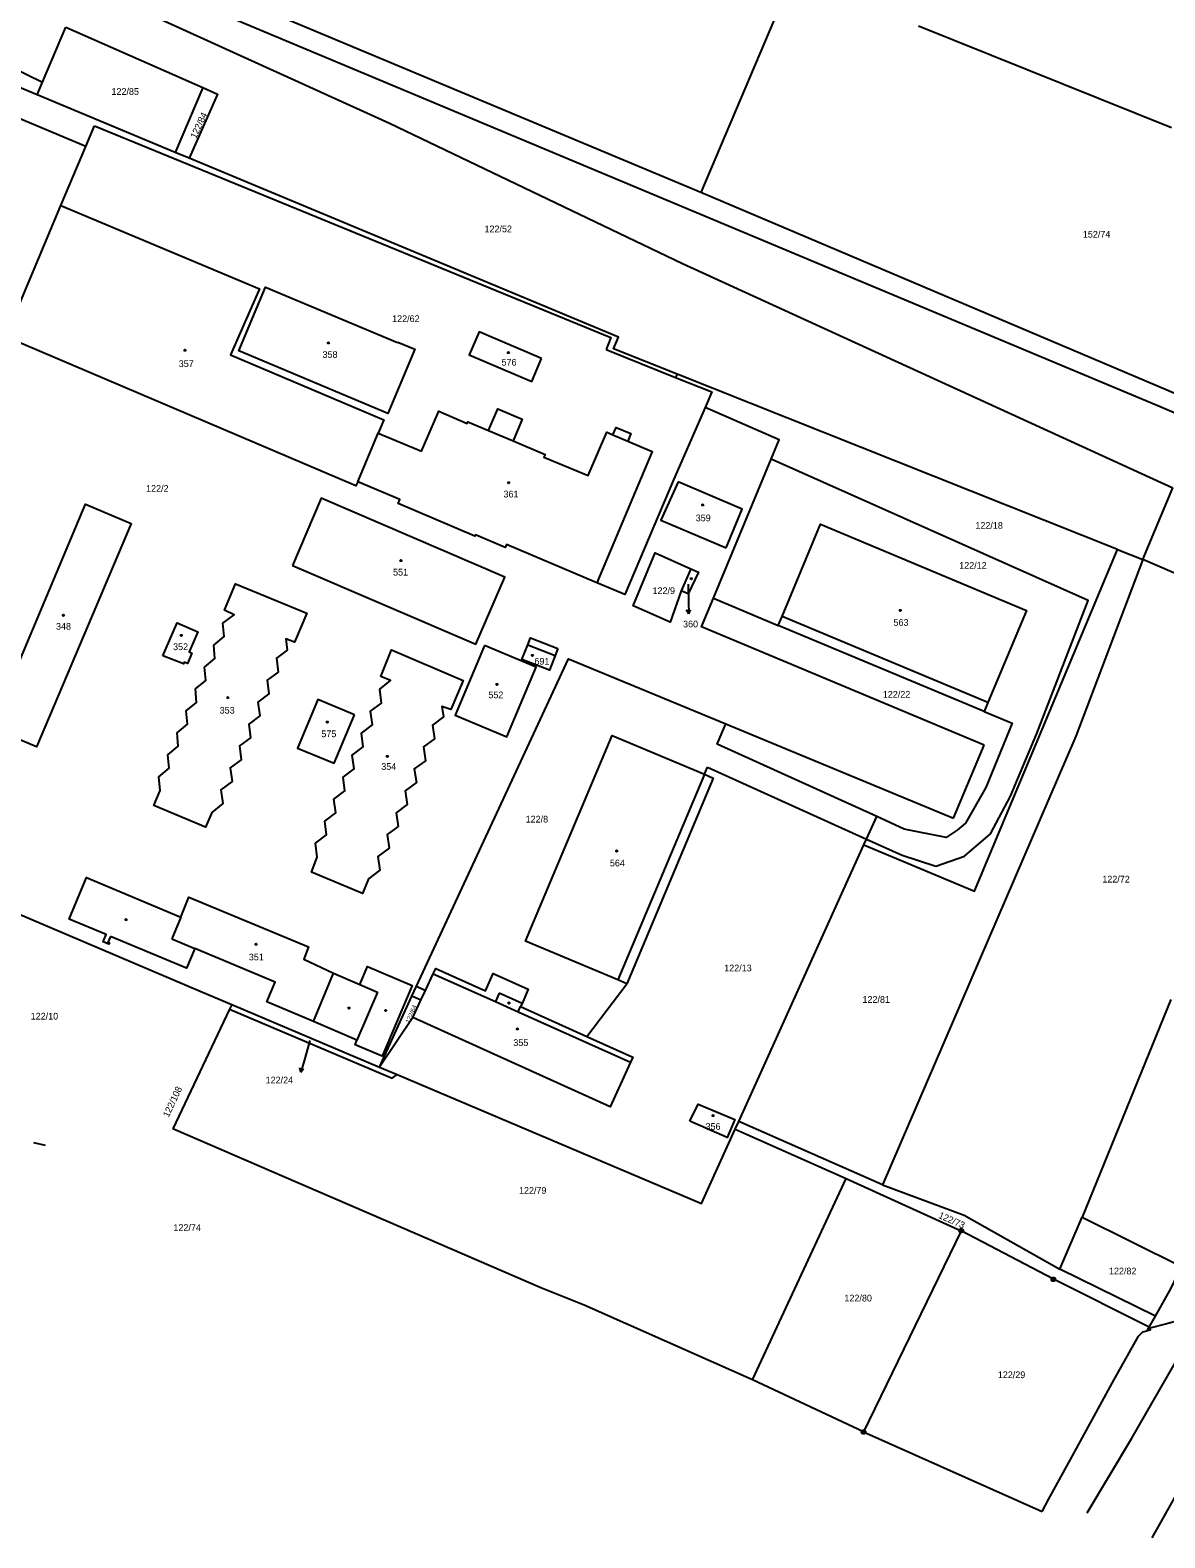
# Model space of a CAD drawing. Extents: x -783948 to -781889, y -1005870 to -1004430.
# Drawn here: x -783525.7 to -783238.5, y -1005192 to -1004810.4 of the extents above; entities that cross this region are included whole.
import ezdxf

# ---------------------------------------------------------------- set-up
doc = ezdxf.new("R2010")
doc.units = 0
for name, color, linetype in [('Vrstva 1', 7, 'Continuous'), ('Vrstva 2', 7, 'Continuous'), ('Vrstva 4', 7, 'Continuous'), ('Vrstva 5', 7, 'Continuous'), ('Vrstva 6', 7, 'Continuous'), ('Vrstva 7', 7, 'Continuous'), ('Vrstva 8', 7, 'Continuous')]:
    doc.layers.add(name, color=color, linetype=linetype)

msp = doc.modelspace()

# ---------------------------------------------------------------- linework, layer by layer
at = {"layer": 'Vrstva 1'}
for p, q in [((-783616.88, -1004777.22), (-783522.54, -1004823.62)), ((-783333.26, -1004797.89), (-783355.91, -1004851.55)), ((-783522.54, -1004823.62), (-783516.61, -1004809.65)), ((-783516.61, -1004809.65), (-783481.95, -1004824.95)), ((-783300.84, -1004809.34), (-783236.85, -1004835.1)), ((-783511.57, -1004839.9), (-783545.36, -1004825.67)), ((-783523.89, -1004826.8), (-783522.54, -1004823.62)), ((-783481.95, -1004824.95), (-783488.93, -1004841.36)), ((-783488.93, -1004841.36), (-783523.89, -1004826.8)), ((-783511.57, -1004839.9), (-783509.36, -1004834.66)), ((-783517.86, -1004854.84), (-783511.57, -1004839.9)), ((-783485.39, -1004842.84), (-783488.93, -1004841.36)), ((-783176.87, -1004927.54), (-783355.91, -1004851.55)), ((-783379.94, -1004891.29), (-783362.32, -1004898.32)), ((-783361.96, -1004897.48), (-783362.32, -1004898.32)), ((-783250.52, -1004941.88), (-783361.96, -1004897.48)), ((-783354.89, -1004905.91), (-783362.87, -1004924.27)), ((-783442.78, -1004924.72), (-783437.56, -1004912.44)), ((-783352.76, -1004954.19), (-783338.15, -1004919.02)), ((-783244.08, -1004944.4), (-783236.49, -1004926.3)), ((-783250.52, -1004941.88), (-783244.08, -1004944.4)), ((-783197.55, -1004964.59), (-783244.08, -1004944.4)), ((-783358.47, -1004946.76), (-783360.89, -1004952.36)), ((-783352.76, -1004954.19), (-783336.36, -1004961.06)), ((-783284.27, -1004982.87), (-783336.36, -1004961.06)), ((-783349.66, -1004986), (-783292, -1005009.86)), ((-783292, -1005009.86), (-783284.27, -1004991.41)), ((-783355.04, -1004998.76), (-783354.26, -1004996.92)), ((-783354.26, -1004996.92), (-783314.01, -1005015.14)), ((-783314.01, -1005015.14), (-783311.44, -1005009.45)), ((-783346.37, -1005086.59), (-783314.69, -1005016.63)), ((-783314.69, -1005016.63), (-783314.01, -1005015.14)), ((-783533.85, -1005031.91), (-783482.02, -1005053.88)), ((-783482.02, -1005053.88), (-783474.65, -1005057.01)), ((-783437.27, -1005072.86), (-783429.08, -1005054.87)), ((-783429.08, -1005054.87), (-783427.93, -1005052.4)), ((-783384.77, -1005065.1), (-783374.68, -1005051.77)), ((-783475.21, -1005058.19), (-783489.52, -1005088.45)), ((-783474.65, -1005057.01), (-783475.21, -1005058.19)), ((-783474.65, -1005057.01), (-783437.27, -1005072.86)), ((-783237.05, -1005055.76), (-783259.43, -1005110.88)), ((-783428.84, -1005060.34), (-783437.27, -1005072.86)), ((-783437.27, -1005072.86), (-783432.8, -1005074.75)), ((-783461.46, -1005100.61), (-783489.52, -1005088.45)), ((-783347.28, -1005088.6), (-783346.37, -1005086.59)), ((-783347.28, -1005088.6), (-783319.15, -1005101.07)), ((-783309.97, -1005102.63), (-783346.37, -1005086.59)), ((-783524.82, -1005091.94), (-783521.86, -1005092.63)), ((-783431.98, -1005113.38), (-783461.46, -1005100.61)), ((-783342.85, -1005152), (-783319.15, -1005101.07)), ((-783319.15, -1005101.07), (-783290.07, -1005114.26)), ((-783265.13, -1005123.98), (-783259.43, -1005110.88)), ((-783259.43, -1005110.88), (-783234.31, -1005123.3)), ((-783396.48, -1005128.76), (-783431.98, -1005113.38)), ((-783290.07, -1005114.26), (-783314.77, -1005165.21)), ((-783240.91, -1005135.88), (-783265.13, -1005123.98)), ((-783242.99, -1005139.6), (-783242.49, -1005138.71)), ((-783314.77, -1005165.21), (-783342.85, -1005152)), ((-783314.77, -1005165.21), (-783269.58, -1005185.36)), ((-783269.58, -1005185.36), (-783267.94, -1005182.33))]:
    msp.add_line(p, q, dxfattribs=at)
for points in [[(-783355.91, -1004851.55), (-783501.59, -1004790.51), (-783555.37, -1004767.38)], [(-783512.01, -1004798.82), (-783434.77, -1004833.99), (-783360.56, -1004869.48), (-783236.49, -1004926.3)], [(-783523.89, -1004826.8), (-783558.98, -1004812.17), (-783592.76, -1004850.42)], [(-783481.95, -1004824.95), (-783478.25, -1004826.59), (-783485.39, -1004842.84)], [(-783509.36, -1004834.66), (-783378.69, -1004888.25), (-783379.94, -1004891.29)], [(-783361.96, -1004897.48), (-783378.03, -1004891.08), (-783376.78, -1004888.09), (-783485.39, -1004842.84)], [(-783442.78, -1004924.72), (-783443.21, -1004925.73), (-783531.85, -1004888.01), (-783517.86, -1004854.84)], [(-783517.86, -1004854.84), (-783467.66, -1004875.89), (-783474.96, -1004892.58), (-783436.13, -1004909.08), (-783437.56, -1004912.44)], [(-783432.63, -1004889.37), (-783428.31, -1004891.18), (-783435.16, -1004907.48), (-783472.89, -1004891.61), (-783466.15, -1004875.51), (-783432.69, -1004889.51), (-783432.63, -1004889.37)], [(-783396.25, -1004893.54), (-783412.08, -1004886.79), (-783414.57, -1004892.63), (-783398.74, -1004899.38), (-783396.25, -1004893.54)], [(-783362.32, -1004898.32), (-783353.18, -1004901.97), (-783354.89, -1004905.91)], [(-783437.56, -1004912.44), (-783426.62, -1004916.97), (-783422.25, -1004906.84), (-783415.04, -1004909.94), (-783414.87, -1004909.53), (-783409.68, -1004911.74), (-783407.34, -1004906.23), (-783401.13, -1004908.86), (-783403.46, -1004914.38), (-783395.36, -1004917.82), (-783395.65, -1004918.51), (-783384.44, -1004923.17), (-783379.72, -1004912.16), (-783378.19, -1004912.83), (-783377.41, -1004910.99), (-783373.67, -1004912.52), (-783374.42, -1004914.44), (-783368.24, -1004917.1), (-783382.23, -1004950.34)], [(-783338.15, -1004919.02), (-783336.1, -1004914.09), (-783354.89, -1004905.91)], [(-783314.01, -1005015.14), (-783305.01, -1005019.21), (-783296.5, -1005022.01), (-783289.25, -1005019.49), (-783282.64, -1005013.85), (-783277.59, -1005004.29), (-783270.94, -1004988.45), (-783257.95, -1004954.74), (-783338.15, -1004919.02)], [(-783382.23, -1004950.34), (-783405.13, -1004940.56), (-783405.46, -1004941.34), (-783413, -1004938.13), (-783413.16, -1004938.5), (-783432.58, -1004930.25), (-783432.15, -1004929.24), (-783442.78, -1004924.72)], [(-783362.87, -1004924.27), (-783375.15, -1004953.22), (-783382.23, -1004950.34)], [(-783361.72, -1004924.73), (-783366.06, -1004934.41), (-783349.57, -1004941.41)], [(-783349.57, -1004941.41), (-783345.51, -1004931.63), (-783361.72, -1004924.73)], [(-783459.3, -1004945.93), (-783412.89, -1004965.84), (-783405.59, -1004948.83), (-783452, -1004928.91), (-783459.3, -1004945.93)], [(-783535.52, -1004987.01), (-783511.69, -1004930.42), (-783500.14, -1004935.26), (-783524.03, -1004991.84), (-783535.52, -1004987.01)], [(-783336.36, -1004961.06), (-783335.41, -1004958.8), (-783325.63, -1004935.46), (-783273.55, -1004957.29), (-783283.33, -1004980.63), (-783284.27, -1004982.87)], [(-783360.89, -1004952.36), (-783363.75, -1004960.27), (-783373.06, -1004956.1), (-783367.48, -1004942.75), (-783358.47, -1004946.76)], [(-783314.69, -1005016.63), (-783286.72, -1005028.34), (-783250.52, -1004941.88)], [(-783244.08, -1004944.4), (-783261.03, -1004989.09), (-783309.97, -1005102.63)], [(-783358.47, -1004946.76), (-783356.5, -1004947.61), (-783359.16, -1004953.11), (-783360.89, -1004952.36)], [(-783462.92, -1004972.88), (-783465.69, -1004974.95), (-783465.25, -1004978.42), (-783468.03, -1004980.5), (-783467.58, -1004983.97), (-783470.37, -1004986.04), (-783469.91, -1004989.51), (-783472.71, -1004991.59), (-783472.24, -1004995.06), (-783475.05, -1004997.14), (-783474.57, -1005000.6), (-783477.39, -1005002.68), (-783476.9, -1005006.15), (-783479.66, -1005008.39), (-783481.3, -1005012.1), (-783494.35, -1005006.63), (-783492.73, -1005002.87), (-783493.12, -1004999.36), (-783490.49, -1004997.2), (-783490.8, -1004993.81), (-783488.18, -1004991.65), (-783488.48, -1004988.26), (-783485.86, -1004986.1), (-783486.16, -1004982.71), (-783483.54, -1004980.55), (-783483.85, -1004977.16), (-783481.22, -1004975), (-783481.53, -1004971.61), (-783478.91, -1004969.45), (-783479.21, -1004966.06), (-783476.59, -1004963.9), (-783476.9, -1004960.51), (-783474.04, -1004958.41), (-783476.51, -1004957.2), (-783473.69, -1004950.56), (-783455.67, -1004958.02), (-783458.74, -1004965.34), (-783460.99, -1004964.51), (-783460.59, -1004967.33), (-783463.35, -1004969.4), (-783462.92, -1004972.88)], [(-783284.27, -1004991.41), (-783355.77, -1004961.44), (-783352.76, -1004954.19)], [(-783492.05, -1004968.75), (-783488.49, -1004960.42), (-783483.25, -1004962.68), (-783485.41, -1004967.77), (-783484.72, -1004968.07), (-783485.86, -1004970.75), (-783486.65, -1004970.42), (-783486.87, -1004970.83), (-783492.05, -1004968.75)], [(-783432.54, -1005011.94), (-783435.35, -1005014.02), (-783434.84, -1005017.48), (-783437.66, -1005019.56), (-783437.14, -1005023.03), (-783440.05, -1005025.22), (-783441.6, -1005028.9), (-783454.51, -1005023.57), (-783453.04, -1005019.77), (-783453.44, -1005016.21), (-783450.64, -1005014.11), (-783451.12, -1005010.64), (-783448.32, -1005008.54), (-783448.8, -1005005.08), (-783446, -1005002.98), (-783446.48, -1004999.51), (-783443.68, -1004997.41), (-783444.16, -1004993.95), (-783441.36, -1004991.85), (-783441.84, -1004988.38), (-783439.04, -1004986.28), (-783439.52, -1004982.81), (-783436.72, -1004980.72), (-783437.2, -1004977.25), (-783434.44, -1004975.02), (-783436.95, -1004974.04), (-783434.21, -1004967.25), (-783416.06, -1004975.03), (-783419.2, -1004982.4), (-783421.47, -1004981.6), (-783421.04, -1004984.22), (-783423.85, -1004986.3), (-783423.34, -1004989.76), (-783426.15, -1004991.84), (-783425.64, -1004995.31), (-783428.45, -1004997.39), (-783427.94, -1005000.85), (-783430.75, -1005002.93), (-783430.24, -1005006.39), (-783433.05, -1005008.48), (-783432.54, -1005011.94)], [(-783410.73, -1004966.19), (-783418.1, -1004983.81), (-783405.03, -1004989.29), (-783397.65, -1004971.64), (-783410.73, -1004966.19)], [(-783392.14, -1004966.96), (-783392.8, -1004968.7), (-783394.28, -1004972.41), (-783401.25, -1004969.68), (-783399.75, -1004965.98), (-783399.02, -1004964.21), (-783392.14, -1004966.96)], [(-783427.93, -1005052.4), (-783389.47, -1004969.54), (-783349.66, -1004986)], [(-783443.57, -1004983.74), (-783452.88, -1004979.86), (-783457.98, -1004992.11), (-783448.73, -1004995.96), (-783443.57, -1004983.74)], [(-783284.27, -1004982.87), (-783277.16, -1004985.84), (-783283.83, -1005002.13), (-783289, -1005011.14), (-783291.12, -1005012.94), (-783293.86, -1005014.79), (-783304.49, -1005012.61), (-783311.44, -1005009.45)], [(-783311.44, -1005009.45), (-783351.81, -1004991.11), (-783349.66, -1004986)], [(-783374.68, -1005051.77), (-783376.99, -1005050.8), (-783400.32, -1005040.96), (-783378.37, -1004988.92), (-783355.04, -1004998.76)], [(-783355.04, -1004998.76), (-783352.79, -1004999.74), (-783374.68, -1005051.77)], [(-783505.33, -1005039.77), (-783505.97, -1005041.29), (-783505.6, -1005041.45), (-783505.73, -1005041.77), (-783507.16, -1005041.17), (-783506.39, -1005039.33), (-783515.82, -1005035.39), (-783511.38, -1005024.92), (-783487.57, -1005034.88), (-783485.54, -1005029.87), (-783455.27, -1005042.46), (-783456.42, -1005045.52), (-783448.87, -1005049.12), (-783442.25, -1005051.95), (-783440.32, -1005047.4), (-783429, -1005052.2), (-783436.58, -1005070.11), (-783443.42, -1005067.21), (-783442.97, -1005066.02), (-783453.99, -1005061.33), (-783465.74, -1005056.33), (-783463.66, -1005051.36), (-783483.99, -1005042.86), (-783486.07, -1005047.83), (-783505.33, -1005039.77)], [(-783427.93, -1005052.4), (-783425.63, -1005053.48), (-783423.66, -1005049.22), (-783422.97, -1005047.89), (-783410.43, -1005053.56), (-783408.46, -1005049.18), (-783399.61, -1005053.17), (-783401.2, -1005056.79), (-783401.55, -1005057.54), (-783384.77, -1005065.1)], [(-783428.84, -1005060.34), (-783426.78, -1005055.95), (-783429.08, -1005054.87)], [(-783475.21, -1005058.19), (-783434.02, -1005075.66), (-783432.8, -1005074.75)], [(-783384.77, -1005065.1), (-783373.18, -1005070.31), (-783373.77, -1005071.61), (-783378.86, -1005082.88), (-783428.84, -1005060.34)], [(-783432.8, -1005074.75), (-783355.79, -1005107.4), (-783347.28, -1005088.6)], [(-783358.7, -1005086.56), (-783356.64, -1005082.23), (-783347.34, -1005086.16), (-783349.3, -1005090.65), (-783358.7, -1005086.56)], [(-783309.97, -1005102.63), (-783289.28, -1005110.36), (-783265.13, -1005123.98)], [(-783242.49, -1005138.71), (-783266.75, -1005126.57), (-783290.07, -1005114.26)], [(-783240.91, -1005135.88), (-783236.96, -1005128.78), (-783234.31, -1005123.3)], [(-783342.85, -1005152), (-783385.46, -1005133.14), (-783396.48, -1005128.76)], [(-783228.42, -1005135.15), (-783228.69, -1005135.29), (-783238.39, -1005137.89), (-783242.37, -1005138.96), (-783242.28, -1005139.41), (-783242.99, -1005139.6)], [(-783242.49, -1005138.71), (-783241.27, -1005136.52), (-783240.91, -1005135.88)], [(-783267.94, -1005182.33), (-783261.89, -1005171.22), (-783251.85, -1005152.84), (-783245.24, -1005140.99), (-783244.09, -1005139.9), (-783242.99, -1005139.6)]]:
    msp.add_lwpolyline(points, dxfattribs=at)
at = {"layer": 'Vrstva 4'}
for p, q in [((-783409.68, -1004911.74), (-783403.46, -1004914.38)), ((-783378.19, -1004912.83), (-783374.42, -1004914.44)), ((-783283.33, -1004980.63), (-783335.41, -1004958.8)), ((-783399.75, -1004965.98), (-783392.8, -1004968.7)), ((-783355.04, -1004998.76), (-783376.99, -1005050.8)), ((-783487.57, -1005034.88), (-783489.82, -1005040.42)), ((-783489.82, -1005040.42), (-783483.99, -1005042.86)), ((-783453.99, -1005061.33), (-783448.87, -1005049.12)), ((-783423.66, -1005049.22), (-783407.91, -1005056.3)), ((-783437.76, -1005053.87), (-783442.97, -1005066.02)), ((-783442.25, -1005051.95), (-783437.76, -1005053.87)), ((-783426.78, -1005055.95), (-783425.63, -1005053.48)), ((-783406.96, -1005054.19), (-783407.91, -1005056.3)), ((-783401.2, -1005056.79), (-783406.96, -1005054.19)), ((-783407.91, -1005056.3), (-783402.19, -1005058.91)), ((-783402.19, -1005058.91), (-783401.55, -1005057.54)), ((-783402.19, -1005058.91), (-783373.77, -1005071.61)), ((-783246.9, -1005166.76), (-783234.67, -1005145.54)), ((-783258.2, -1005185.66), (-783246.9, -1005166.76)), ((-783231.45, -1005173.48), (-783241.83, -1005192))]:
    msp.add_line(p, q, dxfattribs=at)
at = {"layer": 'Vrstva 5'}
for centre in [(-783486.51, -1004891.44), (-783450.18, -1004889.57), (-783404.65, -1004892.04), (-783404.54, -1004924.98), (-783355.48, -1004930.58), (-783431.85, -1004944.67), (-783358.35, -1004949.27), (-783517.25, -1004958.53), (-783305.49, -1004957.29), (-783487.44, -1004963.62), (-783398.56, -1004968.68), (-783475.64, -1004979.34), (-783407.54, -1004976.03), (-783450.49, -1004985.56), (-783435.28, -1004994.25), (-783377.21, -1005018.17), (-783501.38, -1005035.52), (-783468.5, -1005041.78), (-783445.02, -1005057.94), (-783435.71, -1005058.54), (-783404.52, -1005056.64), (-783402.36, -1005063.21), (-783352.84, -1005085.14)]:
    msp.add_circle(centre, 0.175, dxfattribs=at)
at = {"layer": 'Vrstva 6'}
for p, q in [((-783474.69, -1004807.3), (-783239.72, -1004905.69)), ((-783239.72, -1004905.69), (-783060.19, -1004982.81))]:
    msp.add_line(p, q, dxfattribs=at)
at = {"layer": 'Vrstva 7'}
for p, q in [((-783359.12, -1004950.66), (-783359.07, -1004955.12)), ((-783359.07, -1004955.12), (-783359.02, -1004958.12)), ((-783359.02, -1004958.12), (-783359.54, -1004957.13)), ((-783359.02, -1004958.12), (-783358.53, -1004957.11)), ((-783454.87, -1005066.12), (-783456.36, -1005071.26)), ((-783457.19, -1005074.15), (-783457.39, -1005073.04)), ((-783456.36, -1005071.26), (-783457.19, -1005074.15)), ((-783457.19, -1005074.15), (-783456.43, -1005073.32))]:
    msp.add_line(p, q, dxfattribs=at)
at = {"layer": 'Vrstva 8'}
for centre, radius in [((-783290.07, -1005114.26), 0.5), ((-783290.07, -1005114.26), 0.0303), ((-783266.75, -1005126.57), 0.5), ((-783266.75, -1005126.57), 0.0303), ((-783314.77, -1005165.21), 0.5), ((-783314.77, -1005165.21), 0.0303)]:
    msp.add_circle(centre, radius, dxfattribs=at)

# ---------------------------------------------------------------- texts
at = {"layer": 'Vrstva 2'}
for s, p in [('122/85', (-783505.09, -1004826.81)), ('122/52', (-783410.7, -1004861.58)), ('152/74', (-783259.28, -1004862.94)), ('122/62', (-783434.07, -1004884.31)), ('357', (-783488.07, -1004895.69)), ('358', (-783451.68, -1004893.38)), ('576', (-783406.38, -1004895.33)), ('122/2', (-783496.33, -1004927.26)), ('361', (-783405.89, -1004928.7)), ('359', (-783357.25, -1004934.73)), ('122/18', (-783286.48, -1004936.63)), ('551', (-783433.83, -1004948.46)), ('122/12', (-783290.57, -1004946.75)), ('122/9', (-783368.18, -1004953.15)), ('360', (-783360.45, -1004961.59)), ('563', (-783307.2, -1004961.18)), ('348', (-783519.13, -1004962.16)), ('352', (-783489.5, -1004967.33)), ('691', (-783398.06, -1004971.02)), ('552', (-783409.71, -1004979.51)), ('122/22', (-783309.89, -1004979.36)), ('353', (-783477.71, -1004983.4)), ('575', (-783451.97, -1004989.36)), ('354', (-783436.81, -1004997.64)), ('122/8', (-783400.29, -1005010.96)), ('564', (-783378.96, -1005022.07)), ('122/72', (-783254.36, -1005026.15)), ('351', (-783470.32, -1005045.85)), ('122/13', (-783350.03, -1005048.63)), ('122/81', (-783315.05, -1005056.6)), ('122/10', (-783525.53, -1005060.83)), ('355', (-783403.4, -1005067.51)), ('122/24', (-783466.09, -1005076.99)), ('356', (-783354.76, -1005088.74)), ('122/79', (-783401.97, -1005104.93)), ('122/74', (-783489.41, -1005114.33)), ('122/82', (-783252.68, -1005125.32)), ('122/80', (-783319.61, -1005132.18)), ('122/29', (-783280.8, -1005151.58))]:
    msp.add_text(s, height=1.7, dxfattribs=at).set_placement(p)
for s, height, rotation, p in [('122/84', 1.7, 65, (-783483.7, -1004838.02)), ('122/64', 1.14, 67, (-783429.68, -1005061.86)), ('122/108', 1.7, 65, (-783490.62, -1005085.71)), ('122/73', 1.7, 336, (-783295.97, -1005110.98))]:
    msp.add_text(s, height=height, rotation=rotation, dxfattribs=at).set_placement(p)

doc.saveas('drawing.dxf')
